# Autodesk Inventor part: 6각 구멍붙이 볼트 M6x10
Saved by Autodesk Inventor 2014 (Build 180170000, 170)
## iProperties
Created: 2026-05
Part Number: 6각 구멍붙이 볼트 M6x10
Material: 일반
Document SubType Name: Modeling
Designer: dg
Density: 1 g/cm^3
Appearance: 기본값
Author: dg
Author: jhkim
Description: 6각머리 태핑 나사
Creation Date: 2026-04-27
Sending System: Autodesk Inventor 2027
Preprocessor: ST-DEVELOPER v20.1
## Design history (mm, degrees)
node "6각 구멍붙이 볼트 M6x101"
body "Solid1"
node "기준1"
